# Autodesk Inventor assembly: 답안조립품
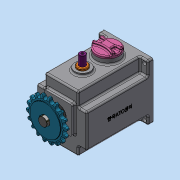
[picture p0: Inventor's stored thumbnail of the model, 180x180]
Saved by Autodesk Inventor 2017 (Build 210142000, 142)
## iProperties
Part Number: 답안조립품
Material: 일반
Document SubType Name: Assembly
Designer: MRC
Author: MRC
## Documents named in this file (16)
- C:\Users\MRC\Desktop\720212V1013\답안조립품.iam
- C:\Users\MRC\Desktop\720212V1013\본체.ipt
- C:\Users\MRC\Desktop\720212V1013\멈춤나사 M3.ipt
- C:\Users\MRC\Desktop\720212V1013\메인 축.ipt
- C:\Users\MRC\Desktop\720212V1013\베어링 608.ipt
- C:\Users\MRC\Desktop\720212V1013\베어링 6003.ipt
- C:\Users\MRC\Desktop\720212V1013\볼트 M4 x 10.ipt
- C:\Users\MRC\Desktop\720212V1013\부시.ipt
- C:\Users\MRC\Desktop\720212V1013\상부 캡.ipt
- C:\Users\MRC\Desktop\720212V1013\서브 축.ipt
- C:\Users\MRC\Desktop\720212V1013\스프로킷.ipt
- C:\Users\MRC\Desktop\720212V1013\슬라이더.ipt
- C:\Users\MRC\Desktop\720212V1013\오일 실 8 x 22 x 7.ipt
- C:\Users\MRC\Desktop\720212V1013\오일 실 17 x 32 x 8.ipt
- C:\Users\MRC\Desktop\720212V1013\커버.ipt
- C:\Users\MRC\Desktop\720212V1013\키 5 x 5.ipt
